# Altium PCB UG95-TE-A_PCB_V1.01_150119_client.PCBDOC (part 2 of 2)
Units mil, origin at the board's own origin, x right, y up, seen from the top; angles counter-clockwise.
Board outline 1460.63 x 2271.65 mil, 4 copper layers (Top, Inner Layer 2, Inner Layer 3, Bottom), stack 35.4 mil thick; 48 components, 69 nets, 290 pads, 828 vias.
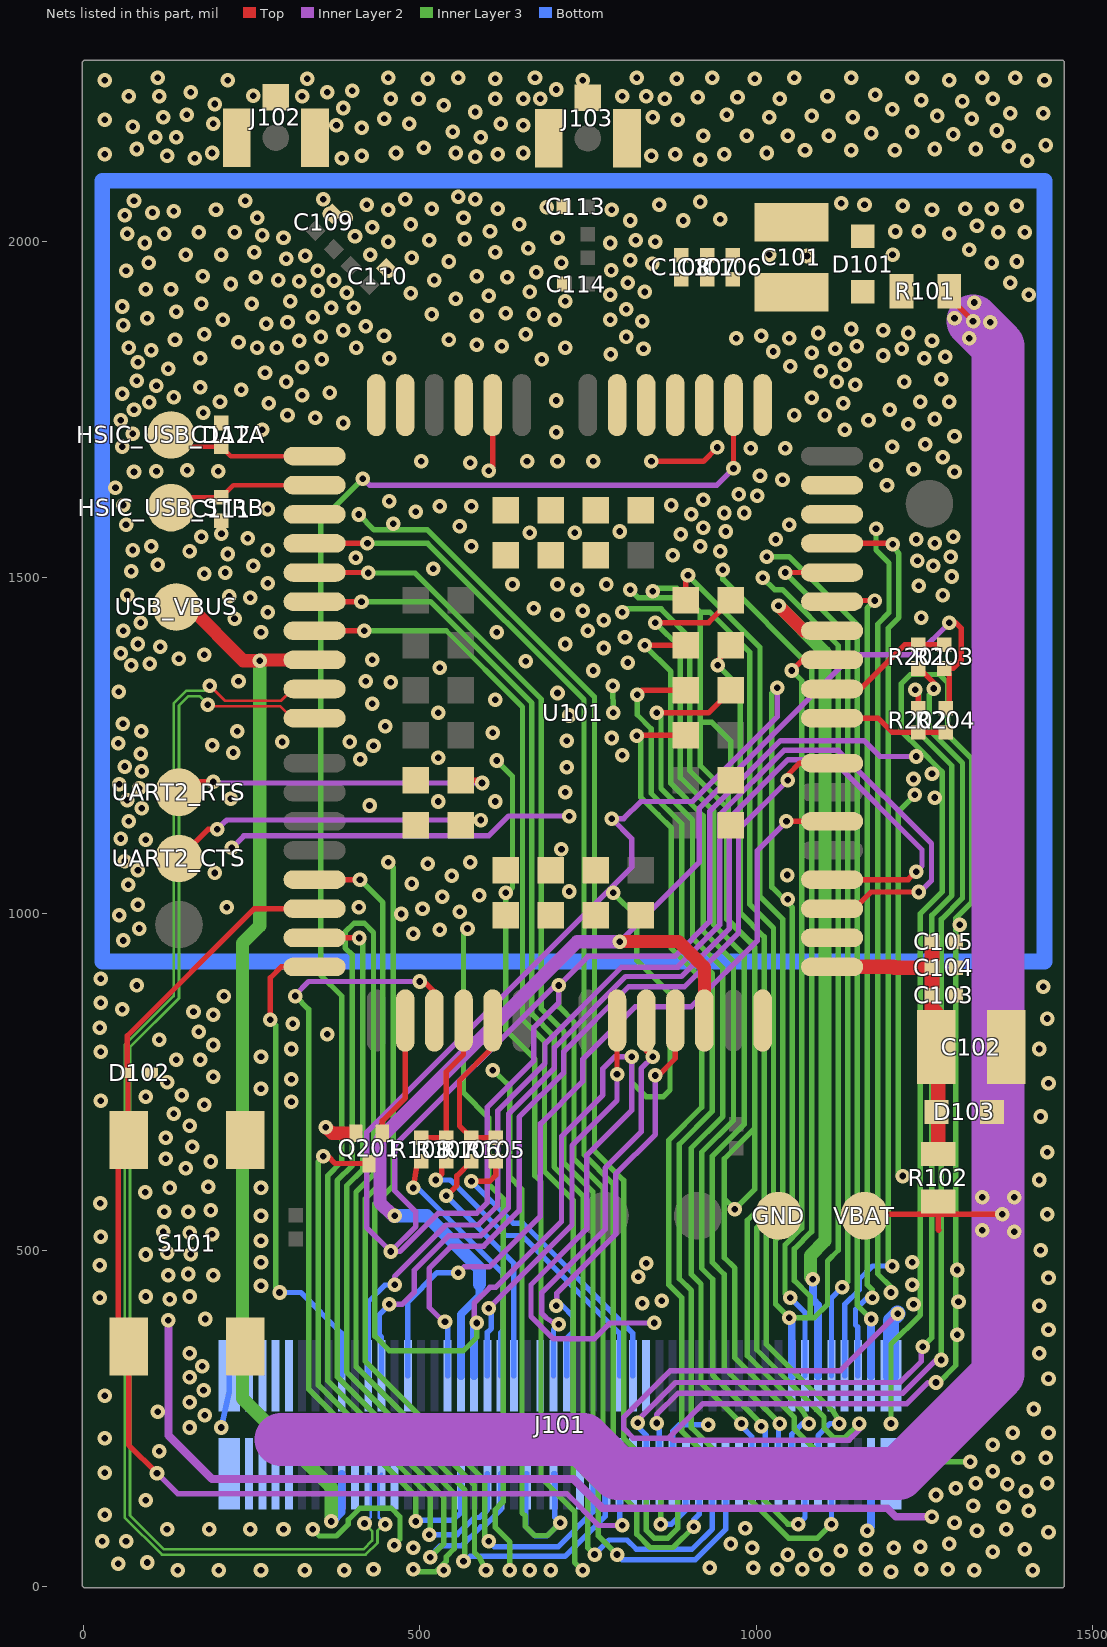
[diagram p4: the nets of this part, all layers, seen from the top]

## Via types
v1: diameter 21.65, hole 9.84, Top to Bottom, 828 vias

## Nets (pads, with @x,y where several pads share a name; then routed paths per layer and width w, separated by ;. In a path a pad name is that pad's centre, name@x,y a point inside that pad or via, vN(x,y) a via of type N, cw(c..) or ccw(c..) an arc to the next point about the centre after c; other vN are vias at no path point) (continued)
GND: C101.2 C102.2 C103.2 C104.2 C105.2 C106.2 C107.2 C108.2 C109.2 C110.1 C111.2 C112.2 C113.2 C114.1 D101.2 D102.2 D103.2 GND.1 J101.1 J101.2 J101.3 J101.4 J101.16 J101.23 J101.33 J101.38 J101.39 J101.47 J101.51 J101.54 J101.55 J101.64 J101.75 J101.81 J101.91 J101.92 J101.93 J101.94 J101.96 J102.2 J102.3 J102.4 J103.2 J103.3 J103.4 Q201.1 S101.1 S101.4 U101.3 U101.31 U101.47 U101.48 U101.50 U101.54 U101.55 U101.58 U101.59 U101.61 U101.62 U101.67 U101.68 U101.69 U101.70 U101.71 U101.72 U101.73 U101.74 U101.79 U101.80 U101.81 U101.82 U101.89 U101.90 U101.91 U101.100 U101.101 U101.102 | length 35709.8
  Top w8: v1(602.36,1659.45) 608.27,1665.35 U101.58@608.27,1756.89 ; v1(844.49,1673.23) 921.61,1673.23 v1(942.32,1693.94)
  Top w19.68: v1(360.24,683.07) 369.57,673.74 Q201.1@404.88,673.74
  Inner Layer 2 w8: v1(220.47,1098.43) 238.19,1116.14 602.36,1116.14 631.89,1145.67 v1(722.44,1145.67) ; v1(584.65,391.73) 580.71,391.73 580.71,421.19 604.18,444.66 612.78,444.66 710.63,542.51 710.63,669.17 772.18,730.72 772.18,770.13 789.44,787.4 v1(814.96,787.4) 814.96,707.93 748.03,641 748.03,531.2 665.35,448.53 665.35,401.65 698.89,368.11 759.23,368.11 782.86,391.73 v1(848.43,391.73) ; v1(1031.5,1336.61) 1031.5,1293.31 905.51,1167.32 828.74,1167.32 803.15,1141.73 v1(785.43,1141.73) 814.96,1112.2 814.96,1069.29 782.29,1036.61 420.79,675.11 420.79,533.94 v1(456.69,498.03) ; v1(1153.54,242.13) 1153.54,232.47 1138.43,217.36 876.67,217.36 871.99,222.05 871.65,222.05 ; v1(1210.63,405.51) 1125.98,320.87 872.63,320.87 803.46,251.7 803.46,234.44 817.44,220.47 870.08,220.47 871.65,222.05 ; v1(1238.19,1234.25) 1184.25,1234.25 1160.63,1257.87 1036.41,1257.87 931.1,1152.57 931.1,988.59 879.52,937.01 750,937.01 v1(706.69,893.7) ; v1(1267.72,303.15) 1255.91,303.15 1224.41,271.65 921.26,271.65 871.65,222.05 ; v1(456.69,498.03) 470.47,498.03 527.56,555.12 584.65,555.12 600.39,570.87 600.39,712.6 669.29,781.5 669.29,830.71 706.69,868.11 v1(706.69,893.7) ; v1(456.69,498.03) 494.09,535.43 494.09,557.09 462.6,588.58 462.6,655.51 700.79,893.7 v1(706.69,893.7)
  Inner Layer 2 w11.81: v1(125.98,395.67) 125.98,259.84 125.98,224.23 190.77,159.45 728.53,159.45 771.83,116.14 1195.16,116.14 1207.84,103.46 v1(1261.69,103.46)
  Inner Layer 3 w8: v1(340.55,84.65) 350.39,74.8 375.91,74.8 393.7,92.59 393.7,98.98 410.86,116.14 457.53,116.14 470.47,103.2 470.47,70.04 v1(461.77,61.34) ; v1(409.17,1594.21) 431.94,1571.45 460.63,1571.45 511.27,1571.45 759.84,1322.87 759.84,647.19 803.15,603.88 803.15,220.84 883.86,140.13 883.86,86.61 868.94,71.69 848.43,71.69 836.61,83.5 836.61,133.86 772.36,198.11 772.36,592.77 729.22,635.91 729.22,839.73 706.69,862.26 v1(706.69,893.7) ; v1(452.76,1076.77) 460.63,1068.9 460.63,1000 460.63,596.46 433.07,568.9 433.07,372.05 454.72,350.39 564.96,350.39 584.65,370.08 v1(584.65,391.73) ; v1(490.16,25.59) 490.16,21.65 523.55,21.65 530.47,28.58 539.37,37.48 539.37,44.2 551.18,56.01 551.18,137.8 377.07,311.91 377.07,603.45 399.61,625.98 399.61,938.98 389.02,949.57 389.02,972.92 402.32,986.22 417.37,986.22 431.1,972.48 431.1,612.2 405.07,586.17 405.07,326.77 581.23,150.61 581.23,50.58 588.58,43.23 v1(598.43,23.62) ; v1(570.87,978.35) 570.87,974.41 564.96,968.5 564.96,734.25 602.36,696.85 602.36,598.43 624.02,576.77 624.02,125.98 612.2,114.17 612.2,87.6 633.86,65.94 v1(633.86,23.62) ; v1(608.27,767.72) 633.86,744.09 633.86,608.5 652.02,590.34 652.02,109.2 656.89,104.33 656.89,89.25 670.51,75.63 689.8,75.63 v1(708.66,94.49) ; v1(614.17,1228.35) 637.8,1204.72 637.8,1039.37 628.94,1030.51 v1@627.95,1029.53 ; v1(627.95,1031.5) v1@627.95,1029.53 ; v1(742.13,23.62) 730.28,35.47 730.28,111.37 680.17,161.48 680.17,601.78 671.05,610.9 671.05,784.13 627.95,827.23 v1@627.95,1029.53 ; v1(787.09,1339.25) v1(787.4,1299.21) ; v1(787.4,1031.5) 822.83,996.06 822.83,931.1 872.05,881.89 872.05,738.19 862.2,728.35 836.61,728.35 814.96,750 v1(814.96,787.4) ; v1(801.18,1448.82) 806.26,1453.9 859.02,1453.9 901.34,1411.58 901.34,1213.37 956.69,1158.02 956.69,992.13 992.13,956.69 ; v1(812.99,1482.28) 824.8,1470.47 846.46,1470.47 895.67,1470.47 ; v1(846.46,1480.31) 850.39,1484.25 881.89,1484.25 895.67,1470.47 ; v1(950.79,1511.81) 950.79,1498.03 1082.68,1366.14 1082.68,527.56 1057.09,501.97 1057.09,454.72 1080.71,431.1 1080.71,399.61 ; v1(1009.84,1500) 1027.46,1482.38 1039.2,1482.38 1122.36,1399.22 1122.36,499.85 1106.3,483.79 1106.3,419.29 1086.61,399.61 1080.71,399.61 ; v1(1015.75,1531.5) 1049.14,1531.5 1150.36,1430.27 1150.36,418.54 v1(1171.26,397.64) ; v1(1031.5,1336.61) 1023.62,1328.74 1023.62,1039.94 1044.57,1018.98 1054.03,1009.53 1054.03,540.25 1029.09,515.3 1029.09,419.73 v1(1049.21,399.61) 1080.71,399.61 ; v1(1153.54,242.13) 1132.68,221.26 1115.43,221.26 1101.18,235.51 1101.18,251.74 1001.09,351.83 1001.09,533.59 1026.03,558.54 1026.03,979.01 990.94,1014.1 990.94,1389.2 931.32,1448.82 917.32,1448.82 ; v1(1178.54,1572.83) 1178.54,1541.34 1197.83,1522.05 1197.83,1448.15 1181.1,1431.41 1181.1,464.57 1200.79,444.88 v1(1200.79,437.01) ; v1(1200.79,242.13) 1200.79,360.24 1244.41,403.86 1244.41,419.29 1244.41,448.82 1244.41,482.28 1244.41,1000.54 1277.22,1033.36 1277.22,1173.23 1277.22,1210.96 1270.67,1217.52 1246.06,1242.13 1215.94,1272.24 1215.94,1342.41 1229.68,1356.14 1273.08,1356.14 1285.38,1343.83 1285.38,1265.91 1321.09,1230.21 1321.09,1017.82 1297.24,993.98 1297.24,984.25 1297.24,470.47 1297.24,423.23 1297.24,374.02 1297.24,328.81 1269.65,301.22 v1(1267.72,303.15) ; v1@1211.81,610.24 1211.81,1152.76 v1(1236.22,1177.17) ; v1(1318.9,185.04) 1106.37,185.04 1057.09,234.33 1057.09,251.16 968.5,339.75 968.5,473.2 952.76,488.95 952.76,576.77 ; 895.67,1470.47 917.32,1448.82 ; 917.32,1285.04 934.25,1285.04 962.6,1256.69 962.6,1183.07 958.66,1179.13 ; 917.32,1285.04 917.32,1448.82 ; 917.32,1285.04 917.32,1220.47 958.66,1179.13 ; 952.76,576.77 v1(968.5,561.02) 998.03,590.55 998.03,681.1 ; 952.76,576.77 952.76,635.83 998.03,681.1 ; 958.66,1179.13 958.66,992.13 992.13,958.66 992.13,956.69 ; 992.13,956.69 998.03,950.79 998.03,681.1
  Bottom w8: J101.55@659.45,167.32 657.54,167.32 657.54,96.52 657.48,96.46 657.48,88.66 671.33,74.8 688.98,74.8 v1(708.66,94.49) 700.72,102.43 700.72,167.32 J101.51@698.82,167.32 ; J101.33@875.98,167.32 875.98,230.47 885.67,240.16 v1(929.13,240.16)
  Bottom w11.81: J101.64@580.71,312.99 580.71,387.8 v1(584.65,391.73) ; v1(1049.21,399.61) 1053.15,395.67 J101.16@1053.15,312.99 ; v1(1165.35,82.68) 1171.26,88.58 J101.3@1171.26,167.32 ; J101.4@1171.26,312.99 v1(1171.26,397.64)
  Bottom w23.62: J101.2@1200.79,312.99 1200.79,395.67 v1(1210.63,405.51) ; 27.56,929.13 27.56,1633.86 27.56,2090.55 1429.13,2090.55 1429.13,929.13 27.56,929.13
  other v1: 1200.79,21.65 139.76,23.62 200.79,23.62 263.78,23.62 328.74,23.62 387.8,23.62 535.43,23.62 663.39,23.62 694.88,23.62 1324.8,23.62 1411.42,23.62 431.1,25.59 1031.5,25.59 1068.9,25.59 1106.3,25.59 1163.39,25.59 1246.06,25.59 1285.43,25.59 931.1,27.56 996.06,27.56 51.18,33.46 94.49,35.43 1047.24,47.24 1088.58,47.24 1352.36,51.18 1125.98,53.15 1163.39,55.12 1399.61,55.12 490.16,57.09 994.09,57.09 1204.72,57.09 1244.09,59.06 962.6,62.99 1287.4,62.99 27.56,66.93 62.99,66.93 1435.04,80.71 1328.74,82.68 124.02,84.65 187.01,84.65 248.03,84.65 297.24,84.65 1372.05,84.65 984.25,86.61 1295.28,94.49 31.5,106.3 1405.51,112.2 1368.11,118.11 1322.83,120.08 92.52,127.95 1267.72,135.83 1401.57,141.73 1297.24,145.67 1374.02,151.57 1326.77,153.54 1433.07,153.54 31.46,168.94 1352.36,171.26 1389.76,190.94 1431.1,190.94 112.2,200.79 1352.36,210.63 31.5,220.47 1381.89,228.35 1435.04,228.35 110.24,259.84 1413.39,263.78 31.5,283.46 1435.04,309.06 1421.26,346.46 1299.21,374.02 1435.04,381.89 181.1,397.64 1421.26,417.32 1234.25,419.29 830.71,421.26 1301.18,423.23 859.65,424.72 127.95,427.17 23.62,429.13 92.52,431.1 157.48,431.1 263.78,446.85 1232.28,448.82 1435.04,458.66 824.8,460.63 125.98,462.6 192.91,462.6 155.51,464.57 1299.21,470.47 23.7,477.44 836.61,480.31 263.78,482.28 1232.28,482.28 92.6,493.54 159.45,494.09 124.02,496.06 1423.23,500 263.78,513.78 25.59,519.68 190.94,523.62 157.48,525.59 118.11,527.56 263.78,551.18 1433.07,553.15 120.08,557.09 155.51,557.09 188.98,559.06 24.88,569.92 91.81,585.87 127.95,592.52 263.78,592.52 185.04,594.49 1421.26,604.33 1218.5,610.24 151.57,622.05 188.98,631.89 122.05,635.83 1433.07,645.67 161.42,653.54 122.05,667.32 157.48,685.04 1423.23,698.82 133.86,702.76 179.13,716.54 309.06,720.47 25.59,722.44 92.52,728.35 145.67,730.31 263.78,740.16 1435.04,748.03 124.02,750 309.06,753.94 192.91,757.87 137.8,783.46 173.23,783.46 263.78,787.4 25.59,795.28 309.06,799.21 1421.26,799.21 192.91,805.12 112.2,812.99 362.2,820.87 171.26,824.8 23.62,830.71 311.02,836.61 1433.07,844.49 192.91,850.39 163.39,854.33 57.09,858.27 25.59,868.11 208.66,877.95 1427.17,891.73 78.74,893.7 25.59,903.54 59.06,960.63 490.16,970.47 529.53,976.38 82.68,978.35 1303.15,984.25 53.15,998.03 472.44,1000 559.41,1003.27 503.94,1007.87 212.6,1009.84 409.45,1009.84 80.71,1013.78 1047.24,1021.65 533.46,1025.59 588.58,1027.56 722.44,1033.46 66.57,1043.74 488.19,1045.28 547.24,1057.09 1046.65,1057.95 194.88,1061.02 80.71,1064.96 511.81,1074.8 574.8,1076.77 61.02,1078.74 710.63,1096.46 92.52,1110.24 55.12,1112.2 66.93,1137.8 86.61,1157.48 425.2,1161.42 527.56,1167.32 612.2,1167.32 64.96,1169.29 218.5,1171.26 1265.75,1173.23 716.54,1181.1 82.68,1187.01 53.15,1192.91 1234.25,1200.79 1261.81,1208.66 86.61,1212.6 718.5,1218.5 61.06,1219.33 411.42,1230.31 527.56,1232.28 801.18,1236.22 84.65,1238.19 222.44,1240.16 431.1,1250 191.06,1251.14 51.18,1253.94 295.28,1255.91 395.67,1255.91 718.5,1257.87 785.43,1261.81 608.27,1269.68 85.67,1272.01 228.35,1271.65 448.82,1279.53 58.43,1283.23 722.44,1295.28 527.56,1299.21 429.13,1312.99 612.2,1318.9 704.72,1328.74 51.93,1330.75 456.69,1344.49 230.32,1346.46 419.29,1346.46 757.87,1362.2 529.53,1366.14 70.87,1370.08 98.43,1372.05 809.06,1374.02 657.48,1375.98 429.13,1377.95 141.73,1379.92 179.13,1385.83 55.12,1387.8 773.62,1395.67 114.17,1397.64 80.71,1401.57 716.54,1401.57 805.12,1411.42 263.78,1419.29 614.17,1419.29 59.06,1421.26 750,1421.26 84.65,1433.07 773.62,1437.01 224.41,1438.98 1246.06,1440.94 704.72,1444.88 273.62,1448.82 742.13,1450.79 669.29,1454.72 248.03,1470.47 216.54,1472.44 64.96,1474.41 1277.56,1474.41 734.25,1482.28 1242.13,1488.19 637.8,1490.16 704.72,1490.16 777.56,1490.16 273.62,1492.13 1291.34,1501.97 179.13,1505.91 210.63,1507.87 70.87,1509.84 519.69,1513.78 251.97,1517.72 1263.78,1517.72 110.24,1519.68 1240.16,1525.59 404.53,1529.61 1289.37,1531.5 875.98,1533.46 214.57,1535.43 157.48,1539.37 946.85,1539.37 72.83,1541.34 273.62,1541.34 100.39,1547.24 576.77,1547.24 917.32,1547.24 1265.75,1551.18 1029.53,1557.09 1238.19,1557.09 244.09,1559.06 175.2,1561.02 1293.31,1561.02 887.8,1564.96 204.92,1565.59 663.39,1566.93 730.32,1566.93 797.24,1568.9 954.72,1568.9 921.26,1574.8 559.06,1576.77 62.99,1578.74 1049.21,1578.74 460.63,1580.71 903.54,1594.49 952.76,1596.46 982.28,1596.46 494.09,1598.43 273.62,1602.36 529.53,1606.3 576.77,1606.3 59.06,1608.27 874.02,1608.27 454.72,1614.17 921.26,1616.14 1001.97,1622.05 974.41,1624.02 47.24,1633.86 1194.88,1637.8 1039.37,1645.67 1005.91,1651.57 74.8,1657.48 108.27,1658.27 200,1658.27 1295.28,1657.48 153.94,1659.84 1234.25,1661.42 1179.13,1667.32 574.8,1671.26 501.97,1673.23 659.45,1673.23 704.72,1673.23 757.87,1673.23 1277.56,1679.13 992.13,1692.91 1043.31,1692.91 57.09,1694.88 1202.76,1694.88 1251.97,1698.82 1295.28,1710.63 72.83,1714.57 702.76,1716.54 265.75,1720.47 1131.89,1720.47 1226.38,1728.35 385.83,1730.31 55.12,1734.25 1167.32,1734.25 1265.75,1736.22 344.49,1738.19 303.15,1742.13 1057.09,1742.13 1102.36,1742.13 177.95,1745.67 74.8,1750 1198.82,1750 275.04,1759.84 1129.92,1759.84 97.24,1761.02 202.76,1761.81 1244.09,1761.81 1287.4,1761.81 702.76,1763.78 1082.68,1767.72 134.25,1768.9 324.8,1771.65 57.09,1773.62 366.14,1775.59 234.25,1779.53 173.23,1783.46 108.27,1785.43 1147.64,1787.4 301.18,1791.34 1120.08,1791.34 1220.47,1791.34 78.74,1793.31 1275.59,1795.28 269.69,1805.12 1096.46,1807.09 125.98,1811.02 324.8,1812.99 1051.18,1814.96 1131.89,1816.93 80.71,1820.87 354.33,1824.8 681.1,1824.8 173.23,1826.77 454.72,1826.77 1250,1826.77 1281.5,1828.74 1188.98,1830.71 783.86,1832.28 1082.68,1834.65 1025.59,1836.61 100.39,1838.58 832.68,1840.55 1118.11,1840.55 1216.54,1840.55 66.93,1842.52 257.87,1842.52 287.4,1842.52 405.51,1842.52 716.54,1842.52 622.05,1844.49 1149.61,1844.49 584.65,1846.46 230.32,1850.39 320.87,1852.36 1261.81,1852.36 135.83,1854.33 543.31,1854.33 970.47,1856.3 1049.21,1856.3 352.36,1858.27 807.09,1858.27 446.65,1859.96 1007.87,1860.24 179.13,1862.2 657.48,1862.2 1092.52,1864.17 1226.38,1864.17 385.83,1868.11 1188.98,1868.11 1141.73,1870.08 419.29,1874.02 59.06,1875.98 271.65,1877.95 303.15,1879.92 830.71,1881.89 206.69,1883.86 700.79,1883.86 783.46,1883.86 94.49,1885.83 340.55,1887.8 584.65,1889.76 517.72,1891.73 669.29,1891.73 627.95,1893.7 137.8,1895.67 807.09,1899.61 368.11,1901.57 401.57,1901.57 57.09,1903.54 175.2,1907.48 250,1907.48 307.09,1911.42 716.54,1911.42 553.15,1915.35 602.36,1919.29 783.46,1921.26 1405.51,1921.26 486.22,1923.23 391.1,1924.17 663.39,1925.2 834.65,1925.2 348.43,1927.17 92.52,1929.13 129.92,1929.13 218.5,1937.01 809.06,1938.98 1377.95,1938.98 320.87,1940.94 372.32,1942.24 289.37,1942.91 521.65,1942.91 255.91,1946.85 629.92,1946.85 177.17,1948.82 584.65,1948.82 673.23,1954.72 62.99,1956.69 348.43,1956.69 452.76,1956.69 784.84,1957.17 845.51,1967.28 96.46,1968.5 710.63,1968.5 1350.39,1968.5 543.31,1970.47 1387.8,1970.47 812.99,1972.44 301.18,1974.41 488.19,1976.38 329.41,1979.09 1075.91,1978.66 151.57,1980.31 204.72,1980.31 426.38,1980.39 1019.8,1980.63 1203.07,1980.63 253.94,1984.25 612.2,1984.25 1316.93,1988.19 661.42,1990.16 90.55,1998.03 783.46,1998.03 452.76,2000 850.39,2000 513.78,2001.97 820.87,2001.97 566.93,2003.94 297.24,2005.91 704.72,2005.91 403.54,2007.87 265.75,2009.84 64.96,2011.81 120.08,2011.81 1287.4,2011.81 171.26,2013.78 224.41,2013.78 1360.24,2013.78 1399.61,2013.78 1207.4,2015.16 604.33,2015.75 1242.13,2015.75 429.13,2021.65 1328.74,2023.62 486.22,2025.59 647.64,2025.59 812.99,2031.5 891.73,2031.5 946.85,2033.46 258.07,2035.63 389.76,2035.43 564.96,2035.43 61.02,2039.37 366.14,2041.77 102.36,2043.31 133.86,2045.28 196.85,2047.24 452.76,2047.24 785.28,2047.24 1261.81,2047.24 517.72,2049.21 616.14,2049.21 1311.02,2049.21 1350.39,2049.21 688.98,2051.18 1218.5,2053.15 1387.8,2053.15 421.26,2055.12 856.3,2055.12 1161.42,2055.12 1126.93,2057.17 917.32,2059.06 74.8,2061.02 240.16,2061.02 356.3,2062.99 478.35,2062.99 582.68,2062.99 557.09,2066.93 1403.54,2120.08 917.32,2122.05 165.35,2124.02 383.86,2124.02 582.68,2125.98 124.02,2127.95 413.39,2127.95 844.49,2127.95 31.5,2129.92 616.14,2129.92 879.92,2129.92 952.76,2129.92 190.94,2131.89 464.57,2131.89 553.15,2131.89 653.54,2131.89 1015.75,2131.89 1072.83,2135.83 1141.73,2135.83 1206.69,2135.83 78.74,2137.8 1265.75,2137.8 1326.77,2137.8 505.91,2139.76 1375.98,2141.73 1431.1,2143.7 106.3,2155.51 137.8,2155.51 590.55,2155.51 921.26,2157.48 986.22,2157.48 1047.24,2157.48 1108.27,2157.48 1293.31,2159.45 1171.26,2161.42 549.21,2163.39 1232.28,2163.39 1358.27,2165.35 413.39,2169.29 72.83,2171.26 375.98,2173.23 653.54,2173.23 192.91,2175.2 484.25,2175.2 620.08,2175.2 31.5,2181.1 883.86,2181.1 446.85,2183.07 1320.87,2183.07 118.11,2185.04 846.46,2185.04 1019.69,2185.04 1143.7,2185.04 1082.68,2187.01 1269.69,2187.01 153.54,2188.98 956.69,2188.98 1377.95,2190.94 1427.17,2190.94 582.68,2192.91 1202.76,2196.85 385.83,2198.82 535.43,2202.76 194.88,2204.72 1307.09,2208.66 1246.06,2210.63 456.69,2212.6 498.03,2212.6 612.2,2212.6 653.54,2212.6 679.13,2212.6 864.17,2212.6 1035.43,2212.6 1352.36,2212.6 913.39,2214.57 972.44,2214.57 66.93,2216.54 112.2,2216.54 252.05,2216.77 324.8,2216.54 801.18,2216.54 836.61,2216.54 1106.3,2216.54 1177.17,2218.5 159.45,2222.44 362.2,2222.44 399.61,2224.41 702.76,2226.38 31.5,2240.16 214.57,2240.16 742.13,2240.16 1287.4,2240.16 1429.13,2240.16 332.68,2242.13 511.81,2242.13 612.2,2242.13 881.89,2242.13 998.03,2242.13 110.24,2244.09 452.76,2244.09 557.09,2244.09 671.26,2244.09 822.83,2244.09 935.04,2244.09 1057.09,2244.09 1141.73,2244.09 1232.28,2244.09 1336.61,2244.09 1385.83,2244.09
HSIC_USB_DATA: C112.1 HSIC_USB_DATA.1 U101.1 | length 226.6
  Top w6.89: HSIC_USB_DATA.1@129.92,1712.6 147.64,1694.88 C112.1@204.72,1694.88 218.5,1681.1 U101.1@343.5,1681.1
HSIC_USB_STRB: C111.1 HSIC_USB_STRB.1 U101.2 | length 227.4
  Top w6.89: HSIC_USB_STRB.1@129.92,1604.33 145.67,1620.08 C111.1@204.72,1620.08 222.44,1637.8 U101.2@343.5,1637.8
I2C_SCL: R202.1 R204.1 U101.40 | length 177.7
  Top w8: U101.40@1113.19,1291.34 1181.73,1291.34 1202.5,1270.57 R202.1@1241.06,1270.57 1241.06,1270.44 R204.1@1282.15,1270.44
I2C_SCL_EVB: J101.37 R202.2 | length 1619.4
  Top w8: v1(1236.77,1333.78) 1241.06,1329.49 R202.2@1241.06,1306.01 1242.92,1306.01 R202.2@1242.92,1304.15
  Inner Layer 2 w8: v1(824.29,243.07) 822.25,245.12 880.28,303.15 1214.45,303.15 1246.06,334.76 1246.06,356.3 v1(1248.03,356.3)
  Inner Layer 3 w8: v1(1236.77,1333.78) 1242.13,1328.43 1242.13,1269.57 1291.22,1220.47 1291.22,1027.56 1261.59,997.92 1261.59,369.86 v1(1248.03,356.3)
  Bottom w8: v1(824.29,243.07) 824.29,237.23 836.61,224.9 J101.37@836.61,167.32
I2C_SDA: R201.1 R203.1 U101.41 | length 193.9
  Top w8: U101.41@1113.19,1334.65 1155.47,1334.65 1221.38,1400.55 R201.1@1241.24,1400.55 R203.1@1279.82,1400.55
I2C_SDA_EVB: J101.35 R201.2 | length 1624.9
  Top w8: R201.2@1241.24,1365.12 1243.27,1365.12 1268.76,1339.63 v1(1264.45,1335.31)
  Inner Layer 2 w8: v1(852.17,242.87) 852.17,255.24 884.33,287.4 1218.5,287.4 1267.72,336.61 v1(1275.59,336.61)
  Inner Layer 3 w8: v1(1264.45,1335.31) 1264.45,1332.68 1257.87,1326.1 1257.87,1273.62 1307.09,1224.41 1307.09,1023.62 1275.59,992.13 v1(1275.59,336.61)
  Bottom w8: v1(852.17,242.87) 856.3,232.28 J101.35@856.3,167.32
JTAG_RTCK: J101.13 U101.96 | length 1536.8
  Top w8: v1(823.35,1326.18) 829.84,1332.68 U101.96@895.67,1332.68
  Inner Layer 3 w8: v1(823.35,1326.18) 823.35,1296.34 844.21,1275.48 844.21,1179.45 889.76,1133.9 889.76,956.69 935.04,911.42 935.04,706.69 885.83,657.48 885.83,457.69 903.74,439.77 903.74,236.09 1047.32,92.52 v1(1062.99,92.52)
  Bottom w8: v1(1062.99,92.52) 1072.83,102.36 J101.13@1072.83,167.32
JTAG_TCK: J101.15 U101.77 | length 1332.5
  Top w8: v1(942.91,1370.08) 942.91,1375.98 U101.77@962.6,1399.61
  Inner Layer 3 w8: v1(942.91,1370.08) 976.77,1336.22 976.77,1001.15 1012.03,965.89 1012.03,569.41 987.01,544.38 987.01,343.12 1068.9,261.23 1080.03,242.91 v1(1078.74,242.13)
  Bottom w8: J101.15@1053.15,167.32 1053.15,226.38 1068.9,242.13 v1(1078.74,242.13)
JTAG_TDI: J101.19 U101.97 | length 1408.8
  Top w8: v1(834.33,1399.68) 895.59,1399.68 U101.97@895.67,1399.61
  Inner Layer 3 w8: v1(834.33,1399.68) 873.34,1360.68 873.34,1194.06 921.26,1146.14 921.26,974.41 966.54,929.13 966.54,692.91 919.29,645.67 919.29,472.88 935.46,456.71 935.46,314.47 1009.81,240.12 v1(1007.87,238.19)
  Bottom w8: v1(1007.87,238.19) 1013.78,232.28 J101.19@1013.78,167.32
JTAG_TDO: J101.11 U101.98 | length 1510.1
  Top w8: U101.98@895.67,1466.54 895.67,1500.59 v1(898.82,1503.74)
  Inner Layer 3 w8: v1(898.82,1503.74) 1005.91,1396.65 1005.91,1026.26 1040.03,992.13 1040.03,547.67 1015.09,522.72 1015.09,360.23 1114.17,261.15 1125.64,243.16 v1(1124.02,242.13)
  Bottom w8: J101.11@1092.52,167.32 1092.52,224.41 1110.24,242.13 v1(1124.02,242.13)
JTAG_TMS: J101.17 U101.78 | length 1508.4
  Top w8: v1(850.39,1433.07) 850.75,1433.43 929.49,1433.43 U101.78@962.6,1466.54
  Inner Layer 3 w8: v1(850.39,1433.07) 887.34,1396.12 887.34,1202.83 937.01,1153.16 937.01,984.25 982.28,938.98 982.28,687.01 935.04,639.76 935.04,481.65 952.76,463.93 952.76,324.8 v1(1035.43,242.13)
  Bottom w8: J101.17@1033.46,167.32 1033.46,240.16 v1(1035.43,242.13)
JTAG_TRST: J101.21 U101.76 | length 1353.8
  Top w8: v1(852.36,1299.21) 929.13,1299.21 U101.76@962.6,1332.68
  Inner Layer 3 w8: v1(852.36,1299.21) 858.77,1292.8 858.77,1186.61 905.51,1139.87 905.51,964.57 950.79,919.29 950.79,698.82 903.54,651.57 903.54,464.3 918.26,449.58 918.26,302.21 v1(978.35,242.13)
  Bottom w8: v1(978.35,242.13) 978.35,238.19 994.09,222.44 J101.21@994.09,167.32
NETLIGHT: J101.65 U101.21 | length 1252.4
  Top w8: v1(500,899.61) 505.91,899.61 521.65,883.86 U101.21@521.65,841.54
  Inner Layer 2 w8: v1(314.96,877.95) 314.96,879.92 334.65,899.61 v1(500,899.61)
  Inner Layer 3 w8: v1(314.96,877.95) 334.65,858.27 334.65,293.31 494.09,133.86 v1(494.09,96.46)
  Bottom w8: v1(494.09,96.46) 494.09,98.43 549.49,98.43 561.02,109.96 J101.65@561.02,167.32
PCM_CLK: J101.31 U101.4 | length 1870.3
  Top w8: U101.4@343.5,1551.18 343.62,1551.3 v1(422.09,1551.3)
  Inner Layer 3 w8: v1(422.09,1551.3) 511.62,1551.3 744.09,1318.82 744.09,641.98 787.4,598.68 787.4,204.49 858.27,133.63 v1(858.27,92.52)
  Bottom w8: v1(858.27,92.52) 874.38,92.52 895.67,113.81 J101.31@895.67,167.32
PCM_IN: J101.25 U101.6 | length 1970.7
  Top w8: U101.6@343.5,1464.57 413.19,1464.57 v1(413.19,1464.49)
  Inner Layer 3 w8: v1(413.19,1464.49) 515.87,1464.49 666.72,1313.63 666.72,850.99 699.79,817.93 699.79,623.6 742.6,580.79 742.6,168.82 765.59,145.83 765.59,74.96 v1(793.31,47.24)
  Bottom w8: v1(793.31,47.24) 801.18,39.37 909.45,39.37 954.72,84.65 J101.25@954.72,167.32
PCM_OUT: J101.27 U101.7 | length 1945.4
  Top w8: U101.7@343.5,1421.26 v1(417.32,1421.26)
  Inner Layer 3 w8: v1(417.32,1421.26) 539.3,1421.26 652.72,1307.83 652.72,843.34 685.39,810.67 685.39,617.27 728.03,574.63 728.03,161.74 750,139.76 750,57.09 v1(759.84,47.24)
  Bottom w8: v1(759.84,47.24) 781.5,68.9 808.33,68.9 822.11,55.12 904.65,55.12 935.04,85.51 J101.27@935.04,167.32
PCM_SYNC: J101.29 U101.5 | length 1903.7
  Top w8: U101.5@343.5,1507.87 422.52,1507.87 v1(423.15,1507.24)
  Inner Layer 3 w8: v1(423.15,1507.24) 492.91,1507.24 680.72,1319.43 680.72,858.77 714.5,824.99 714.5,629.75 757.48,586.78 757.48,178.45 822.61,113.32 822.61,77.7 842.63,57.69 876.59,57.69 v1(907.48,88.58)
  Bottom w8: v1(907.48,88.58) 907.48,99.13 915.35,107.01 J101.29@915.35,167.32
PWRDWN_N: D102.1 J101.41 S101.2 S101.3 U101.16 | length 1872.5
  Top w8: v1(109.02,168.35) 66.93,210.43 S101.3@66.93,356.81 51.34,372.4 S101.2@51.34,648.31 ; U101.16@343.5,1007.87 253.94,1007.87 64.96,818.9 D102.1@64.96,763.78 65.87,762.87 65.87,664.96 S101.2@66.93,663.9 ; S101.2@51.34,648.31 S101.2@66.93,663.9 ; S101.2@51.34,648.31 51.34,663.9 S101.2@66.93,663.9
  Inner Layer 2 w8: v1(109.02,168.35) 139.57,137.8 718.5,137.8 765.75,90.55 v1(801.18,90.55)
  Bottom w8: J101.41@797.24,167.32 797.24,94.49 v1(801.18,90.55)
PWRKEY: J101.45 U101.15 | length 1389.1
  Top w8: U101.15@343.5,1051.18 375,1051.18 v1(410.98,1051.14)
  Inner Layer 3 w8: v1(410.98,1051.14) 445.1,1017.02 445.1,602.58 419.07,576.55 419.07,334.65 596.46,157.26 596.46,72.83 v1(602.36,66.93)
  Bottom w8: v1(602.36,66.93) 610.24,59.06 705.91,59.06 757.87,111.02 J101.45@757.87,167.32
RESET_ALL_N: J101.9 U101.95 | length 1548.2
  Top w8: v1(822.68,1265.12) 823.31,1265.75 U101.95@895.67,1265.75
  Inner Layer 3 w8: v1(822.68,1265.12) 828.74,1259.06 828.74,1173.23 854.33,1147.64 874.02,1127.95 874.02,948.82 919.29,903.54 919.29,712.6 870.08,663.39 870.08,448.69 889.74,429.03 889.74,230.29 1048.35,71.69 1091.38,71.69 v1(1112.2,92.52)
  Bottom w8: v1(1112.2,92.52) J101.9@1112.2,167.32
RESET_N: J101.43 U101.17 | length 1383.9
  Top w8: U101.17@343.5,964.57 409.57,964.57 v1(409.84,964.29)
  Inner Layer 3 w8: v1(409.84,964.29) 415.35,958.78 415.35,620.08 391.07,595.8 391.07,318.9 566.93,143.04 566.93,37.4 v1(564.96,37.4)
  Bottom w8: v1(564.96,37.4) 567.76,37.4 574.8,44.45 715.93,44.45 775.65,104.17 775.65,167.32 J101.43@777.56,167.32
RI: J101.68 U101.39 | length 1278.1
  Top w8: v1(1047.24,1198.82) 1047.24,1206.69 1064.96,1224.41 U101.39@1113.19,1224.41
  Inner Layer 2 w8: v1(537.4,393.7) 536.3,392.6 513.78,415.11 513.78,472.48 547.2,505.91 594.83,505.91 647.64,558.71 647.64,697.84 714.13,764.33 714.13,795.29 810.64,891.81 893.72,891.81 973.97,972.06 973.97,1125.54 v1(1047.24,1198.82)
  Bottom w8: v1(537.4,393.7) 541.34,389.76 J101.68@541.34,312.99
RTS: J101.74 U101.37 | length 1215.2
  Top w8: v1(1045.28,1137.8) U101.37@1113.19,1137.8
  Inner Layer 2 w8: v1(557.09,466.54) 565.66,475.11 603.63,475.11 679.13,550.61 679.13,687.82 742.13,750.81 742.13,783.69 820.64,862.2 903.72,862.2 1001.97,960.46 1001.97,1094.49 v1(1045.28,1137.8)
  Bottom w8: J101.74@482.28,312.99 482.28,423.15 525.67,466.54 v1(557.09,466.54)
SIM_CLK: J101.8 U101.46 | length 1385.9
  Top w8: U101.46@1113.19,1551.18 1202.2,1551.18 v1(1203.27,1550.12)
  Inner Layer 3 w8: v1(1202.76,476.38) 1196.85,482.28 1196.85,1425.2 1212.6,1440.94 1212.6,1535.13 v1(1203.27,1550.12)
  Bottom w8: J101.8@1131.89,312.99 1131.89,419.29 1153.54,440.94 1153.54,456.69 1173.23,476.38 v1(1202.76,476.38)
SIM_DATA: J101.10 U101.45 | length 1313.3
  Top w8: v1(1043.31,1507.87) U101.45@1113.19,1507.87
  Inner Layer 3 w8: v1(1043.31,1507.87) 1136.36,1414.82 1136.36,453.29 v1(1127.95,444.88)
  Bottom w8: J101.10@1112.2,312.99 1112.2,429.13 v1(1127.95,444.88)
SIM_PRESENCE: J101.14 U101.42 | length 1145.8
  Top w8: v1(1053.15,1362.2) 1068.9,1377.95 U101.42@1113.19,1377.95
  Inner Layer 3 w8: v1(1051.18,429.13) 1049.21,429.13 1043.09,435.26 1043.09,507.88 1068.07,532.86 1068.07,1347.28 v1(1053.15,1362.2)
  Bottom w8: v1(1051.18,429.13) 1072.83,407.48 J101.14@1072.83,312.99
SIM_RST: J101.6 U101.44 | length 1241.5
  Top w8: U101.44@1113.19,1464.57 1114.84,1466.22 v1(1176.42,1466.22)
  Inner Layer 3 w8: v1(1173.23,429.13) 1173.23,440.94 1165.35,448.82 1165.35,1455.16 v1(1176.42,1466.22)
  Bottom w8: J101.6@1151.57,312.99 1151.57,385.43 1148.07,388.93 1148.07,411.85 1165.35,429.13 v1(1173.23,429.13)
SIM_VDD: J101.12 U101.43 | length 1283.7
  Top w19.68: v1(1033.46,1458.66) 1070.87,1421.26 U101.43@1113.19,1421.26
  Inner Layer 3 w8: v1@1081.34,460.43 1084.65,457.13 v1(1084.65,456.69)
  Inner Layer 3 w19.68: v1(1033.46,1458.66) 1102.52,1389.61 1102.52,513.7 1080.87,492.05 v1@1080.87,459.84
  Bottom w11.81: v1(1084.65,456.69) 1084.65,426.06 1092.52,418.19 J101.12@1092.52,312.99
SPI_CLK: J101.62 U101.26 | length 614
  Top w8: v1(793.31,761.81) U101.26@793.31,841.54
  Inner Layer 2 w8: v1(602.36,413.39) 726.38,537.4 726.38,655.66 793.31,722.59 v1(793.31,761.81)
  Bottom w8: J101.62@600.39,312.99 600.39,377.81 606.3,383.71 606.3,413.39 v1(602.36,413.39)
SPI_MISO: J101.60 R108.2 | length 387.2
  Top w8: v1(490.16,592.52) 495.18,625.1 495.18,631.93 R108.2@502.01,631.93
  Bottom w8: v1(490.16,592.52) 496.88,592.52 624.02,465.38 624.02,380.85 620.08,376.92 J101.60@620.08,312.99
SPI_MOSI: J101.58 R106.2 | length 375.9
  Top w8: v1(539.37,580.71) 555.12,596.46 555.12,610.55 R106.2@576.5,631.93
  Bottom w8: v1(539.37,580.71) 639.76,480.31 J101.58@639.76,312.99
SPI_MRDY: J101.50 U101.28 | length 626
  Top w8: v1(850.39,759.84) 852.44,757.8 879.92,785.28 U101.28@879.92,841.54
  Inner Layer 2 w8: v1(702.76,417.32) 703.74,418.31 703.74,436.02 791.34,523.62 791.34,613.02 850.39,672.07 v1(850.39,759.84)
  Bottom w8: v1(702.76,417.32) 711.87,417.32 728.35,400.85 728.35,379.16 718.5,369.31 J101.50@718.5,312.99
SPI_SRDY: J101.52 U101.27 | length 620.9
  Top w8: U101.27@836.61,841.54 836.61,797.24 v1(846.46,787.4)
  Inner Layer 2 w8: v1(706.69,389.76) 705.38,387.8 687.73,399.61 681.1,406.24 681.1,436.42 775.59,530.91 775.59,622.05 829.26,675.72 829.26,770.21 v1(846.46,787.4)
  Bottom w8: J101.52@698.82,312.99 698.82,381.89 v1(706.69,389.76)
STATUS: Q201.2 U101.20 | length 181.9
  Top w8: Q201.2@444.25,673.74 444.25,692.28 478.35,726.38 U101.20@478.35,841.54
STATUS_N: J101.61 Q201.3 | length 865.2
  Top w8: v1(356.3,639.76) 363.11,639.76 374.02,628.86 Q201.3@424.57,628.86
  Inner Layer 3 w8: v1(356.3,639.76) 356.3,639.12 349.07,631.89 349.07,299.18 515.75,132.51 515.75,76.77 v1(513.78,76.77)
  Bottom w8: v1(513.78,76.77) 555.52,76.77 581.11,102.36 588.95,102.36 600.39,113.81 J101.61@600.39,167.32
UART1_RXD: J101.80 U101.34 | length 1767.7
  Top w8: U101.34@1113.19,1007.87 1146.46,1007.87 1171.26,1032.68 v1(1242.13,1032.68)
  Inner Layer 2 w8: v1(462.6,448.82) 462.6,460.9 539.1,537.4 586.73,537.4 616.14,566.82 616.14,707.74 686.13,777.73 686.13,806.89 800.28,921.04 883.35,921.04 945.97,983.65 945.97,1147.64 1041.82,1243.49 1122.1,1243.49 1261.02,1104.57 1261.02,1049.61 1244.09,1032.68 v1(1242.13,1032.68)
  Bottom w8: J101.80@423.23,312.99 423.23,423.23 447.57,447.57 v1(462.6,448.82)
UART1_TXD: J101.78 U101.35 | length 1677.9
  Top w8: U101.35@1113.19,1051.18 1226.38,1051.18 v1(1238.19,1062.99)
  Inner Layer 2 w8: v1(454.72,419.29) 473.71,419.29 491.43,437.01 491.43,469.93 543.15,521.65 590.78,521.65 631.89,562.76 631.89,702.82 700.13,771.06 700.13,801.09 806.08,907.04 889.15,907.04 959.97,977.85 959.97,1141.73 1047.72,1229.49 1112.96,1229.49 1246.85,1095.6 1246.85,1071.65 v1(1238.19,1062.99)
  Bottom w8: J101.78@442.91,312.99 442.91,370.83 439.8,373.94 439.8,404.37 v1(454.72,419.29)
UART2_CTS: U101.88 UART2_CTS.1 | length 509.9
  Top w8: UART2_CTS.1@141.73,1082.68 185.04,1125.98 v1(198.82,1125.98) ; U101.88@561.02,1131.89 561.02,1139.76 v1(590.55,1139.76)
  Inner Layer 2 w8: v1(198.82,1125.98) 211.75,1138.92 212.11,1138.92 212.96,1139.76 v1(590.55,1139.76)
UART2_RTS: U101.87 UART2_RTS.1 | length 493.6
  Top w8: UART2_RTS.1@141.73,1181.1 141.73,1185.04 153.54,1196.85 v1(192.91,1196.85) ; U101.87@561.02,1198.82 588.58,1198.82 v1(592.52,1194.88)
  Inner Layer 2 w8: v1(192.91,1196.85) 194.88,1194.88 v1(592.52,1194.88)
UART2_RXD: J101.42 R107.2 | length 469.4
  Top w8: v1(523.62,604.33) 532.66,613.37 532.66,631.93 R107.2@539.49,631.93
  Bottom w8: v1(523.62,604.33) 545.28,604.26 627.8,521.73 651.65,521.73 797.24,376.14 J101.42@797.24,312.99
UART2_RXD/SPI_MISO: R107.1 R108.1 U101.22 | length 222.2
  Top w8: R108.1@502.01,667.36 R107.1@539.49,667.36 539.49,765.75 564.96,791.22 U101.22@564.96,841.54
UART2_TXD: J101.40 R105.2 | length 457.5
  Top w8: v1(576.77,602.36) 603.98,602.36 612.72,611.1 R105.2@612.72,631.93
  Bottom w8: v1(576.77,602.36) 639.14,539.99 653.19,539.99 816.93,376.26 J101.40@816.93,312.99
UART2_TXD/SPI_MOSI: R105.1 R106.1 U101.23 | length 246.7
  Top w8: R106.1@582.68,673.54 R106.1@576.5,667.36 ; U101.23@608.27,841.54 608.27,801.18 559.06,751.97 559.06,684.8 R106.1@576.5,667.36 ; R105.1@612.72,667.36 R106.1@576.5,667.36
USB+: J101.77 U101.9 | length 1999.6
  Top w4.33: v1(187.4,1339.76) 210.04,1317.13 293.5,1317.13 309.11,1332.74 343.01,1332.74 U101.9@343.5,1334.65
  Inner Layer 3 w3.94: v1(187.4,1339.76) 179.92,1332.28 152.66,1332.28 133.76,1313.39 133.76,877.85 61.02,805.11 61.02,102.36 116.24,47.15 419.47,47.15 437.01,64.69 437.01,82.68 446.85,92.52 v1(448.82,92.52)
  Bottom w3.94: J101.77@442.91,167.32 438.98,163.39 438.98,102.36 v1(448.82,92.52)
USB-: J101.79 U101.10 | length 1951.8
  Top w3.94: v1(184.8,1311.26) 187.01,1309.06 292.32,1309.06 310.04,1291.34 U101.10@343.5,1291.34
  Inner Layer 3 w3.94: v1(184.8,1311.26) 172.05,1324.02 155.91,1324.02 141.73,1309.84 141.73,874.68 68.9,801.85 68.9,105.62 119.5,55.02 416.21,55.02 429.13,67.95 429.13,82.05 v1(417.68,93.5)
  Bottom w3.94: v1(417.68,93.5) 427.17,102.99 427.17,163.39 J101.79@423.23,167.32
USB_VBUS: J101.83 U101.8 USB_VBUS.1 | length 1663.5
  Top w19.68: USB_VBUS.1@137.8,1456.69 157.52,1456.69 237.4,1376.81 v1(261.85,1376.81) 262.99,1377.95 U101.8@343.5,1377.95
  Inner Layer 3 w19.68: v1(261.85,1376.81) 261.85,982.32 236.22,956.69 236.22,279.53 368.11,147.64 v1(368.11,96.46)
  Bottom w11.81: v1(368.11,96.46) 370.24,96.46 383.86,110.24 J101.83@383.86,167.32
VBAT: J101.95 J101.97 J101.98 J101.99 J101.100 R101.1 R102.1 VBAT.1 | length 3112.5
  Top w7.87: R101.1@1287.4,1925.98 1289.37,1924.02 1289.37,1915.35 v1(1322.83,1881.89)
  Top w8: VBAT.1@1163.86,553.15 1271.22,553.15 ; R102.1@1271.22,572.36 1271.22,553.15 ; 1271.65,529.57 1271.22,530 1271.22,553.15 ; v1(1366.14,553.15) 1271.22,553.15
  Inner Layer 2 w78.74: 293.31,218.5 743.29,218.5 793.8,167.99 1212.03,167.99 1360.24,316.19 1360.24,527.56 1360.24,529.53 1360.24,553.15 1360.24,578.74 1360.24,1844.49 1336.61,1868.11 1332.68,1872.05 v1(1322.83,1881.89)
  Bottom w8: v1(204.72,236.22) 216.54,289.37 J101.100@216.54,312.99
  other v1: 157.48,236.22 180.28,254.53 157.48,273.62 178.27,291.54 157.48,311.02 176.22,327.28 157.48,346.46 1383.86,527.56 1336.61,529.53 1336.61,578.74 1383.86,578.74 1316.93,1856.3 1348.43,1879.92 1295.28,1885.83 1324.8,1909.45
VBAT_BB: C102.1 C103.1 C104.1 C105.1 D103.1 R102.2 U101.32 U101.33 | length 533.2
  Top w21.65: U101.32@1113.19,921.26 1204.67,921.26 1205.77,920.16 C104.1@1261.81,920.16 ; C105.1@1261.81,958.94 C104.1@1261.81,920.16 ; C102.1@1267.91,802.05 1267.91,854.13 1261.81,860.24 ; D103.1@1268.54,705.71 D103.1@1271.22,703.03 ; R102.2@1271.22,643.23 D103.1@1271.22,703.03 ; 1261.81,860.24 C103.1@1261.81,878.82 C104.1@1261.81,920.16 ; 1261.81,860.24 1261.81,802.05 1261.81,777.99 1271.22,768.58 1271.22,705.71 D103.1@1271.22,703.03
VBAT_RF: C101.1 C106.1 C107.1 C108.1 D101.1 R101.2 U101.52 U101.53
VDD_1V8: J101.66 R203.2 R204.2 U101.29 | length 2051.7
  Top w8: R204.2@1283.46,1305.87 1287.4,1309.81 1287.4,1357.54 R203.2@1279.82,1365.12 1293.31,1365.12 1305.12,1376.93 1305.12,1425.2 1297.24,1433.07 v1(1287.4,1433.07)
  Top w11.81: R204.2@1282.15,1305.87 R204.2@1283.46,1305.87
  Top w19.68: v1(797.24,958.66) 797.76,959.17 884.49,959.17 923.23,920.43 U101.29@923.23,841.54
  Inner Layer 2 w8: v1(797.24,958.66) 915.35,1076.77 915.35,1156.62 1144.56,1385.83 1240.16,1385.83 v1(1287.4,1433.07)
  Inner Layer 2 w19.68: v1(462.6,551.18) 460.32,551.18 440.63,570.87 440.63,665.35 733.94,958.66 v1(797.24,958.66)
  Bottom w11.81: J101.66@561.02,312.99 561.02,404.53 588.58,432.09 588.58,448.82
  Bottom w19.68: v1(462.6,551.18) 510.16,551.18 588.58,472.76 588.58,448.82
VRTC: J101.59 U101.51 | length 2579.7
  Top w8: v1(966.54,1662.68) U101.51@966.54,1756.89
  Inner Layer 2 w8: v1(415.35,1647.64) 425.2,1637.8 941.65,1637.8 v1(966.54,1662.68)
  Inner Layer 3 w8: v1(415.35,1647.64) 352.36,1584.65 352.36,909.45 383.86,877.95 383.86,631.89 363.07,611.1 363.07,305.49 535.43,133.13 535.43,62.99 v1(515.75,43.31)
  Bottom w8: v1(515.75,43.31) 515.75,45.28 530.97,60.5 562.77,60.5 590.63,88.36 594.74,88.36 620.08,113.7 J101.59@620.08,167.32
WDISABLE#: J101.84 U101.18 | length 727.3
  Top w8: v1(277.56,842.52) 277.56,905.15 293.67,921.26 U101.18@343.5,921.26
  Inner Layer 3 w8: v1(277.56,842.52) 285.43,834.65 285.43,442.91 v1(291.34,437.01)
  Bottom w8: v1(291.34,437.01) 322.99,437.01 383.86,376.14 J101.84@383.86,312.99
pads on no net: J101.5 J101.7 J101.18 J101.20 J101.22 J101.24 J101.26 J101.28 J101.30 J101.32 J101.34 J101.36 J101.44 J101.46 J101.48 J101.49 J101.56 J101.63 J101.67 J101.69 J101.71 J101.73 J101.82 J101.85 J101.86 J101.87 J101.89 J101.90 U101.11 U101.12 U101.13 U101.14 U101.49 U101.57 U101.63 U101.64 U101.65 U101.66 U101.83 U101.84 U101.85 U101.86 U101.99

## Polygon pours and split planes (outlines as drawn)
GND on Top "Top-GND" (solid, pour order 1001): 180,2250 1375,2250 1410,2215 1420,2205 1420,1720 1420,660 1395,635 1375,615 1250,615 1240,615 1210,645 1200,655 1200,1315 1200,1845 1185,1860 1165,1880 940,1880 195,1880 175,1900 165,1910 155,1910 155,2225 180,2250
GND on Top "Top-GND" (solid, pour order 1000): 445,1660 990,1660 995,1660 1020,1635 1020,1565 1020,985 995,960 980,945 505,945 475,945 435,985 435,1650 445,1660
GND on Top "Top-GND" (solid, remove dead copper, pour order 1000): -125.89,2325.58 1553.24,2325.58 1553.24,-28.75 -125.89,-28.75
GND on Inner Layer 2 "Inner Layer 2-GND" (solid, remove dead copper, pour order 1001): -128.46,2299.92 1560.51,2299.92 1560.51,-80 -128.46,-80
GND on Inner Layer 3 "Inner Layer 3-GND" (solid, remove dead copper, pour order 1002): -102.87,2299.92 1560.51,2299.92 1560.51,-48.5 -102.87,-48.5
GND on Bottom "Bottom-GND" (solid, remove dead copper, pour order 1003): -124.53,2299.92 1564.45,2299.92 1564.45,-58.35 -124.53,-58.35

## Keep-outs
Keep-Out Layer:
  lines w3.94: 0,0 0,2267.72 1456.69,2267.72 1456.69,0 0,0

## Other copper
Top:
  region net VBAT: 1141.73,513.78 1124.02,531.5 1124.02,578.74 1137.8,592.52 1389.76,592.52 1399.61,582.68 1399.61,521.65 1391.73,513.78 1141.73,513.78
  region net VBAT_BB: 1059.06,966.54 1070.87,978.35 1261.81,978.35 1273.62,966.54 1273.62,868.11 1302.17,839.57 1302.17,631.89 1290.35,620.08 1234.25,620.08 1222.44,631.89 1222.44,812.99 1151.57,883.86 1070.87,883.86 1059.06,895.67 1059.06,966.54
  region net GND: 550.08,1814.8 629.92,1814.8 629.92,1698.39 550.08,1698.39 550.08,1814.8
  pour cut-out: 721.57,1814.96 778.43,1814.96 778.43,1696.85 721.57,1696.85 721.57,1814.96
  region net VBAT_RF: 864.17,1722.44 875.98,1710.63 931.1,1710.63 940.94,1720.47 940.94,1872.05 960.63,1891.73 1234.25,1891.73 1242.13,1899.61 1242.13,1950.79 1234.25,1958.66 883.86,1958.66 864.17,1938.98 864.17,1722.44
  region net GND: 401.65,1814.96 493.19,1814.96 493.19,1698.35 401.65,1698.35 401.65,1814.96
  region net GND: 287.4,1608.27 397.64,1608.27 397.64,1574.8 287.4,1574.8 287.4,1608.27
  region net GND: 777.56,1818.9 856.18,1818.9 856.18,1690.94 777.56,1690.94 777.56,1818.9
  pour cut-out: 493.23,1815.04 550.08,1815.04 550.08,1698.39 493.23,1698.39 493.23,1815.04
  region net VBAT: 1267.72,1956.69 1255.91,1944.88 1255.91,1893.7 1316.28,1833.32 1327.42,1833.32 1373.37,1879.27 1373.37,1890.41 1307.09,1956.69 1267.72,1956.69
Inner Layer 2:
  pour cut-out: 193.27,1631.57 216.22,1631.57 216.22,1608.5 193.27,1608.5 193.27,1631.57
  pour cut-out: 193.31,1706.3 216.26,1706.3 216.26,1683.23 193.31,1683.23 193.31,1706.3
  pour cut-out: 501.97,1813.43 541.34,1813.43 541.34,1708.66 501.97,1708.66 501.97,1813.43
  pour cut-out: 732.28,2074.8 767.72,2074.8 767.72,1704.72 732.28,1704.72 732.28,2074.8
  pour cut-out: 724.41,2179.13 724.41,2072.83 775.59,2072.83 775.59,2179.13 724.41,2179.13
  region net VBAT: 222.44,358.27 214.57,366.14 147.64,366.14 139.76,358.27 139.76,228.35 188.98,179.13 332.68,179.13 332.68,257.87 242.13,257.87 222.44,277.56 222.44,358.27
  pour cut-out: 259.84,2177.36 311.02,2177.36 311.02,2091.11 311.05,2089.48 311.15,2087.86 311.32,2086.24 311.55,2084.63 311.85,2083.03 312.22,2081.44 312.65,2079.87 313.15,2078.32 313.71,2076.8 314.33,2075.29 315.02,2073.82 315.76,2072.37 316.57,2070.95 317.43,2069.57 318.35,2068.23 319.32,2066.92 320.34,2065.66 321.42,2064.44 322.55,2063.27 512.6,1873.24 514.39,1871.4 516.14,1869.51 517.84,1867.57 519.49,1865.59 521.08,1863.56 522.63,1861.5 524.11,1859.39 525.55,1857.25 526.92,1855.07 528.24,1852.86 529.5,1850.61 530.7,1848.33 531.84,1846.02 532.92,1843.68 533.93,1841.31 534.89,1838.92 535.78,1836.5 536.61,1834.06 537.37,1831.6 538.07,1829.12 538.71,1826.62 539.27,1824.11 539.78,1821.58 540.21,1819.04 540.58,1816.49 540.89,1813.93 541.12,1811.36 541.29,1808.79 541.39,1806.22 541.43,1803.64 541.42,1803.64 541.42,1795.04 500.55,1795.04 500.56,1801.48 500.52,1803.86 500.42,1806.23 500.24,1808.61 499.99,1810.97 499.66,1813.33 499.27,1815.67 498.81,1818.01 498.27,1820.33 497.67,1822.63 496.99,1824.91 496.25,1827.17 495.44,1829.4 494.57,1831.62 493.62,1833.8 492.61,1835.95 491.54,1838.08 490.4,1840.17 489.2,1842.22 487.94,1844.24 486.62,1846.21 485.24,1848.15 483.8,1850.05 482.31,1851.9 480.76,1853.7 479.15,1855.46 477.5,1857.16 477.49,1857.16 277.13,2057.5 275.73,2058.95 274.38,2060.45 273.08,2061.99 271.84,2063.58 270.64,2065.2 269.51,2066.87 268.43,2068.58 267.41,2070.32 266.46,2072.09 265.56,2073.9 264.72,2075.73 263.95,2077.6 263.24,2079.49 262.6,2081.4 262.02,2083.33 261.51,2085.28 261.07,2087.25 260.69,2089.23 260.38,2091.22 260.14,2093.22 259.97,2095.23 259.87,2097.25 259.83,2099.26 259.84,2099.26 259.84,2177.36
Bottom:
  region net VBAT: 244.09,366.14 251.97,358.27 251.97,250 271.65,230.31 271.65,114.17 263.78,106.3 159.45,106.3 143.7,122.05 143.7,354.33 155.51,366.14 244.09,366.14

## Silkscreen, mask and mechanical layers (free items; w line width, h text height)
Silkscreen Top:
  text "DIV" at 597.24,2155.51 h19.68
  text "MAIN" at 121.65,2154.72 h19.68
  text "62" at 420.87,1835 h23.62
  text "50" at 983.23,1832.01 h23.62
  text "HSIC_D" at 40.16,1763.78 h19.68
  text "1" at 251.18,1663.86 h23.62
  text "49" at 1182.83,1663.15 h23.62
  text "CLK_32K" at 1212.2,1533.86 h19.68
  text "HSIC_S" at 42.13,1532.28 h19.68
  text "USB_VBUS" at 51.18,1387.8 h19.68
  text "RTS2" at 30.71,1134.25 h19.68
  text "CTS2" at 27.17,1038.19 h19.68
  text "EFUSE" at 27.17,916.54 h19.68
  text "18" at 242.32,905.98 h23.62
  text "32" at 1182.56,902.44 h23.62
  text "31" at 994.8,735.08 h23.62
  text "19" at 404.33,727.56 h23.62
  text "V1.01" at 1297.24,427.17 h29.53
  text "FRM_SYNC" at 783.46,334.65 h19.68 r90
  text "FRM_CYCLE" at 925.2,314.96 h19.68 r90
  text "PWR_DWN" at 74.8,265.75 h19.68
Silkscreen Bottom:
  lines w3.94: 240.56,454.02 1224.82,454.02 1224.82,847.72 240.56,847.72 240.56,454.02
  text "H101" at 783.11,2117.56 h19.68
  text "LABEL POSITION" at 1084.21,625.94 h50
Paste Mask Bottom:
  lines w23.62: 27.56,929.13 27.56,962.51 ; 27.56,997.94 27.56,1049.12 ; 27.56,1084.55 27.56,1135.73 ; 27.56,1171.17 27.56,1222.35 ; 27.56,1257.78 27.56,1308.96 ; 27.56,1344.4 27.56,1395.58 ; 27.56,1431.01 27.56,1482.19 ; 27.56,1517.62 27.56,1568.81 ; 27.56,1604.24 27.56,1655.42 ; 27.56,1690.85 27.56,1742.03 ; 27.56,1777.47 27.56,1828.65 ; 27.56,1864.08 27.56,1915.26 ; 27.56,1950.7 27.56,2001.88 ; 27.56,2037.31 27.56,2088.49 ; 60.26,2090.55 118.92,2090.55 ; 62.87,929.13 125.87,929.13 ; 177.17,929.13 240.16,929.13 ; 177.17,2090.55 228.35,2090.55 ; 263.78,2090.55 314.96,2090.55 ; 275.59,929.13 326.77,929.13 ; 350.39,2090.55 401.57,2090.55 ; 362.2,929.13 413.39,929.13 ; 437.01,2090.55 488.19,2090.55 ; 448.82,929.13 500,929.13 ; 523.62,2090.55 574.8,2090.55 ; 535.43,929.13 586.61,929.13 ; 610.24,2090.55 661.42,2090.55 ; 622.05,929.13 673.23,929.13 ; 696.85,2090.55 748.03,2090.55 ; 708.66,929.13 759.84,929.13 ; 783.46,2090.55 834.65,2090.55 ; 795.28,929.13 846.46,929.13 ; 870.08,2090.55 921.26,2090.55 ; 881.89,929.13 933.07,929.13 ; 956.69,2090.55 1007.87,2090.55 ; 968.5,929.13 1019.69,929.13 ; 1043.31,2090.55 1094.49,2090.55 ; 1055.12,929.13 1106.3,929.13 ; 1129.92,2090.55 1181.1,2090.55 ; 1141.73,929.13 1192.91,929.13 ; 1216.54,2090.55 1267.72,2090.55 ; 1228.35,929.13 1279.53,929.13 ; 1307.19,2090.55 1384.4,2090.55 ; 1328.95,929.13 1380.13,929.13 ; 1429.13,929.13 1429.13,962.62 ; 1429.13,998.06 1429.13,1049.24 ; 1429.13,1084.67 1429.13,1135.85 ; 1429.13,1171.29 1429.13,1222.47 ; 1429.13,1257.9 1429.13,1309.08 ; 1429.13,1344.51 1429.13,1395.7 ; 1429.13,1431.13 1429.13,1482.31 ; 1429.13,1517.74 1429.13,1568.92 ; 1429.13,1604.36 1429.13,1655.54 ; 1429.13,1690.97 1429.13,1742.15 ; 1429.13,1777.59 1429.13,1828.77 ; 1429.13,1864.2 1429.13,1915.38 ; 1429.13,1950.81 1429.13,2001.99 ; 1429.13,2037.43 1429.13,2088.61
Solder Mask Bottom:
  lines w27.56: 27.56,929.13 27.56,2090.55 1429.13,2090.55 1429.13,929.13 27.56,929.13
